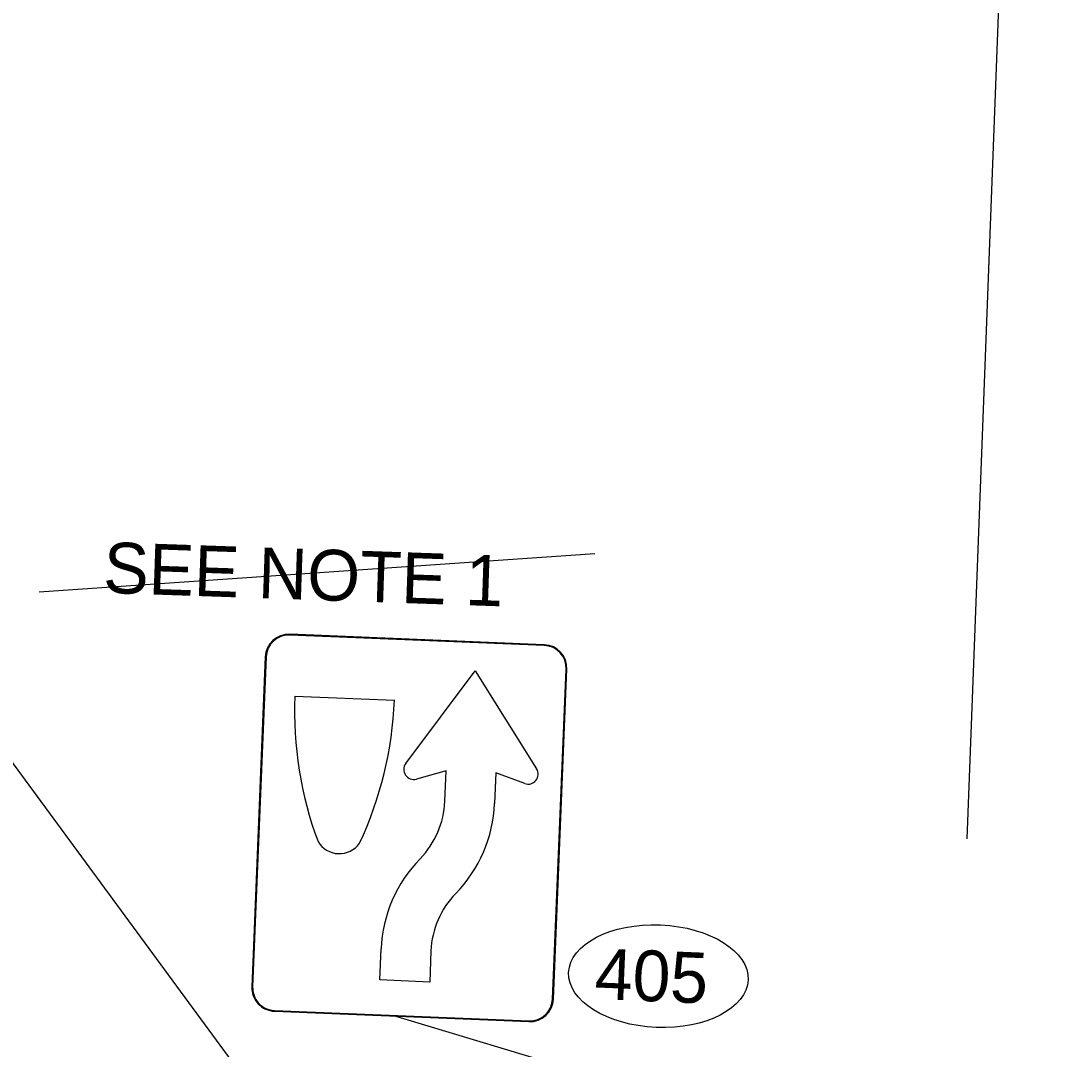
# Model space of a CAD drawing. Extents: x 2096670 to 2098561, y 684033 to 689893.
# Drawn here: x 2097456.3 to 2097702.4, y 686951.8 to 687194.8 of the extents above; entities that cross this region are included whole.
import ezdxf

# ---------------------------------------------------------------- set-up
doc = ezdxf.new("R2010")
doc.units = 0
for name, color, linetype in [('Exist Sign E Speed Limit XX CELL', 7, 'Continuous'), ('Prop DSN Text', 7, 'Continuous'), ('Prop Sign E Keep Right CELL', 7, 'Continuous'), ('Prop Sign E One Way_Right CELL', 7, 'Continuous'), ('Scratch_Level_3', 7, 'Continuous'), ('Scratch_Level_4', 7, 'Continuous')]:
    doc.layers.add(name, color=color, linetype=linetype)

# ---------------------------------------------------------------- blocks, each defined once
blk = doc.blocks.new('R4_7A')
at = {"layer": 'Prop Sign E Keep Right CELL'}
blk.add_line((0.563, 6.375), (2.563, 6.375), dxfattribs=at)
blk.add_line((0.563, 6.375), (2.563, 6.375), dxfattribs=at)
blk.add_line((0.563, 6.375), (2.563, 6.375), dxfattribs=at)
for points in [[(2.841, 5.115), (4.156, 7.031), (5.471, 5.115)], [(2.841, 5.115), (4.156, 7.031), (5.471, 5.115)], [(2.841, 5.115), (4.156, 7.031), (5.471, 5.115)], [(3.656, 4.387), (3.656, 4.998), (3.067, 4.811)], [(3.656, 4.387), (3.656, 4.998), (3.067, 4.811)], [(3.656, 4.387), (3.656, 4.998), (3.067, 4.811)], [(5.246, 4.811), (4.656, 4.998), (4.656, 4.387)], [(5.246, 4.811), (4.656, 4.998), (4.656, 4.387)], [(5.246, 4.811), (4.656, 4.998), (4.656, 4.387)], [(3.5, 1.375), (3.5, 0.75), (2.5, 0.75), (2.5, 1.375)], [(3.5, 1.375), (3.5, 0.75), (2.5, 0.75), (2.5, 1.375)], [(3.5, 1.375), (3.5, 0.75), (2.5, 0.75), (2.5, 1.375)]]:
    blk.add_lwpolyline(points, dxfattribs=at)
for centre, radius, start, end in [((8.062, 6.373), 7.5, 179.9823, 202.7267), ((8.062, 6.373), 7.5, 179.9823, 202.7267), ((8.062, 6.373), 7.5, 179.9823, 202.7267), ((-4.938, 6.373), 7.5, 337.2733, 0.0177), ((-4.938, 6.373), 7.5, 337.2733, 0.0177), ((-4.938, 6.373), 7.5, 337.2733, 0.0177), ((3.006, 5.001), 0.2, 145.5508, 287.601), ((3.006, 5.001), 0.2, 145.5508, 287.601), ((3.006, 5.001), 0.2, 145.5508, 287.601), ((5.306, 5.001), 0.2, 252.399, 34.4492), ((5.306, 5.001), 0.2, 252.399, 34.4492), ((5.306, 5.001), 0.2, 252.399, 34.4492), ((1.906, 4.387), 1.75, 317.9924, 0), ((1.906, 4.387), 1.75, 317.9924, 0), ((1.906, 4.387), 1.75, 317.9924, 0), ((1.906, 4.387), 2.75, 317.9924, 0), ((1.906, 4.387), 2.75, 317.9924, 0), ((1.906, 4.387), 2.75, 317.9924, 0), ((1.562, 3.75), 0.5, 213.3458, 326.6542), ((1.562, 3.75), 0.5, 213.3458, 326.6542), ((1.562, 3.75), 0.5, 213.3458, 326.6542), ((5.25, 1.375), 2.75, 137.9924, 180), ((5.25, 1.375), 2.75, 137.9924, 180), ((5.25, 1.375), 2.75, 137.9924, 180), ((5.25, 1.375), 1.75, 137.9924, 180), ((5.25, 1.375), 1.75, 137.9924, 180), ((5.25, 1.375), 1.75, 137.9924, 180)]:
    blk.add_arc(centre, radius, start, end, dxfattribs=at)

msp = doc.modelspace()

# ---------------------------------------------------------------- linework, layer by layer
at = {"layer": 'Exist Sign E Speed Limit XX CELL'}
msp.add_line((2097432.41, 687049.18), (2097532.69, 686912.94), dxfattribs=at)
at = {"layer": 'Prop Sign E Keep Right CELL'}
for p, q in [((2097580.01, 687047.36), (2097519.89, 687049.81)), ((2097580, 687047.17), (2097519.88, 687049.63)), ((2097514.09, 687044.47), (2097510.92, 686966.53)), ((2097514.28, 687044.46), (2097511.1, 686966.53)), ((2097581.99, 686963.64), (2097585.17, 687041.57)), ((2097582.17, 686963.63), (2097585.35, 687041.57)), ((2097516.26, 686960.74), (2097516.26, 686960.92)), ((2097516.26, 686960.92), (2097576.39, 686958.47)), ((2097516.26, 686960.74), (2097516.26, 686960.92)), ((2097516.26, 686960.74), (2097576.38, 686958.29))]:
    msp.add_line(p, q, dxfattribs=at)
for centre, radius, start, end in [((2097519.66, 687044.25), 5.57, 87.665, 177.665), ((2097519.66, 687044.25), 5.39, 87.665, 177.665), ((2097579.79, 687041.79), 5.57, 357.665, 87.665), ((2097579.79, 687041.79), 5.39, 357.665, 87.665), ((2097516.49, 686966.31), 5.57, 177.665, 267.665), ((2097516.49, 686966.31), 5.39, 177.665, 267.665), ((2097576.61, 686963.86), 5.57, 267.665, 357.665), ((2097576.61, 686963.86), 5.39, 267.665, 357.665)]:
    msp.add_arc(centre, radius, start, end, dxfattribs=at)
at = {"layer": 'Prop Sign E One Way_Right CELL'}
msp.add_line((2097544.37, 686959.78), (2097716.41, 686908.02), dxfattribs=at)
msp.add_ellipse((2097606.98, 686969.04), major_axis=(-21.2, 0.88), ratio=0.571429, dxfattribs=at)
at = {"layer": 'Scratch_Level_3'}
msp.add_line((2097591.99, 687068.85), (2097460.69, 687059.77), dxfattribs=at)
at = {"layer": 'Scratch_Level_4'}
msp.add_line((2097679.91, 687001.49), (2097698.1, 687475.8), dxfattribs=at)

# ---------------------------------------------------------------- block references
at = {"layer": 'Prop Sign E Keep Right CELL', "xscale": 11.767345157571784, "yscale": 11.767345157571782, "rotation": -2.335003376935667}
msp.add_blockref('R4_7A', (2097511.43, 686960.52), dxfattribs=at)

# ---------------------------------------------------------------- texts
at = {"layer": 'Prop DSN Text'}
msp.add_text('SEE NOTE 1', height=12, rotation=358.0495, dxfattribs=at).set_placement((2097475.69, 687059.62))
at = {"layer": 'Prop Sign E One Way_Right CELL'}
msp.add_text('405', height=11.98, rotation=357.6309, dxfattribs=at).set_placement((2097591.78, 686963.67))

doc.saveas('drawing.dxf')
